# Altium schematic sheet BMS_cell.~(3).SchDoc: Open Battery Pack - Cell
size A4; Date: 26/03/2019; Author: Morgane Vallée - Samuel Lesueur; Revision: 1.0; SheetNumber: 3; SheetTotal: 3
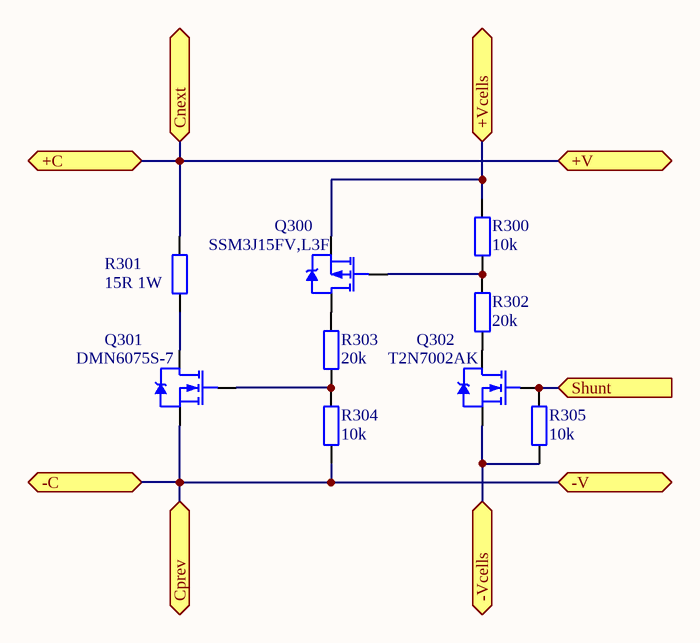
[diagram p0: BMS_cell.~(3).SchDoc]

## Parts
Q300  SSM3J15FV,L3F  [DIODES SOT-23-3]
Q301  DMN6075S-7  [DIODES SOT-23-3]
Q302  T2N7002AK  [DIODES SOT-23-3]
R300  10k  [R0603]
R301  15R 1W  [STACKPOLE CSR2512]
R302  20k  [R0603]
R303  20k  [R0603]
R304  10k  [R0603]
R305  10k  [R0603]

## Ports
+C, +V, +Vcells, -C, -V, -Vcells, Cnext, Cprev, Shunt (in)

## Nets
+C: R301.2 ; port +C, port Cnext, port +V
+Vcells: Q300.2(S) R300.2 ; port +Vcells
-C: Q301.2(S) R304.1 ; port -C, port Cprev, port -V
-Vcells: Q302.2(S) R305.1 ; port -Vcells
Shunt: Q302.1(G) R305.2 ; port Shunt
NetQ300_1: Q300.1(G) R300.1 R302.2
NetQ300_3: Q300.3(D) R303.2
NetQ301_1: Q301.1(G) R303.1 R304.2
NetQ301_3: Q301.3(D) R301.1
NetQ302_3: Q302.3(D) R302.1

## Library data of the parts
Q300 = MOSFET_P
Q301 Q302 = MOSFET_N
R300-R305 = Res2: Resistor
